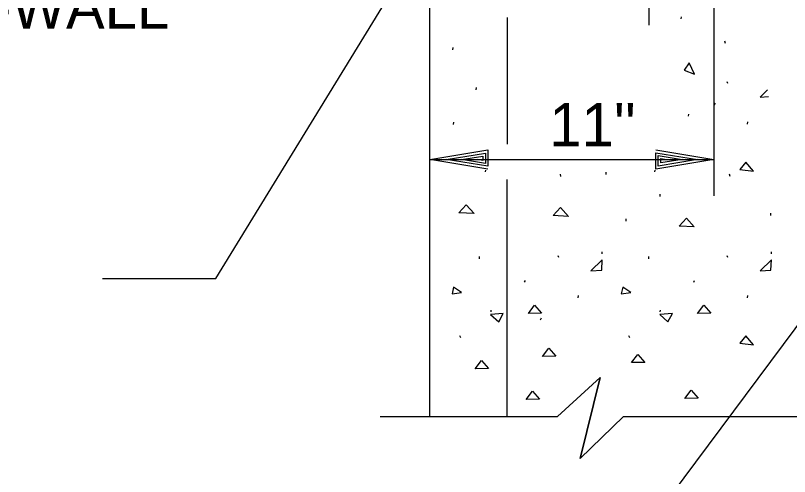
# Model space of a CAD drawing. Extents: x 22369.6 to 22428.3, y 22369.6 to 22415.
# Drawn here: x 22391.587 to 22394.904, y 22374.706 to 22376.682 of the extents above; entities that cross this region are included whole.
import ezdxf

# ---------------------------------------------------------------- set-up
doc = ezdxf.new("R2010")
doc.units = 0
for name, color, linetype in [('Level 1', 7, 'Continuous'), ('Level 10', 7, 'Continuous'), ('Level 4', 7, 'Continuous'), ('Level 8', 7, 'Continuous')]:
    doc.layers.add(name, color=color, linetype=linetype)

msp = doc.modelspace()

# ---------------------------------------------------------------- linework, layer by layer
at = {"layer": 'Level 1'}
for p, q in [((22394.3031, 22376.6397), (22394.3031, 22379.7381)), ((22394.5795, 22378.9163), (22394.5795, 22375.9096)), ((22392.4456, 22375.5546), (22394.1777, 22378.3806)), ((22394.7241, 22376.2165), (22394.7255, 22376.2261)), ((22393.3634, 22376.0646), (22394.5795, 22376.0646)), ((22393.3634, 22376.0646), (22393.3634, 22376.0646)), ((22393.4324, 22376.0646), (22393.4324, 22376.0646)), ((22394.5105, 22376.0646), (22394.5105, 22376.0646)), ((22394.5795, 22376.0646), (22394.5795, 22376.0646)), ((22393.602, 22376.0119), (22393.6033, 22376.0193)), ((22394.3272, 22376.0119), (22394.3285, 22376.0193)), ((22394.1914, 22374.3506), (22395.2279, 22375.7422)), ((22393.9153, 22375.6452), (22393.9125, 22375.6523)), ((22391.9597, 22375.5546), (22392.4456, 22375.5546)), ((22393.9096, 22374.963), (22394.0929, 22375.1307)), ((22394.0073, 22374.7831), (22394.0929, 22375.1307)), ((22394.0929, 22375.1307), (22394.0073, 22374.7831)), ((22393.1508, 22374.963), (22393.9096, 22374.963)), ((22394.1931, 22374.963), (22394.0073, 22374.7831)), ((22394.0073, 22374.7831), (22394.1931, 22374.963)), ((22394.1931, 22374.963), (22395.6847, 22374.963))]:
    msp.add_line(p, q, dxfattribs=at)
for points in [[(22393.6115, 22376.0235), (22393.3634, 22376.0646), (22393.6115, 22376.1057), (22393.6115, 22376.0354), (22393.4324, 22376.0646), (22393.6009, 22376.0924), (22393.6009, 22376.0473), (22393.4987, 22376.0646), (22393.5902, 22376.0792), (22393.5902, 22376.0606), (22393.5677, 22376.0646)], [(22394.3314, 22376.1057), (22394.5795, 22376.0646), (22394.3314, 22376.0235), (22394.3314, 22376.0938), (22394.5105, 22376.0646), (22394.342, 22376.0367), (22394.342, 22376.0818), (22394.4442, 22376.0646), (22394.3526, 22376.05), (22394.3526, 22376.0686), (22394.3752, 22376.0646)]]:
    msp.add_lwpolyline(points, dxfattribs=at)
at = {"layer": 'Level 10'}
for p, q in [((22393.3634, 22374.963), (22393.3634, 22379.6997)), ((22393.695, 22376.6724), (22393.695, 22376.1298)), ((22393.695, 22374.963), (22393.695, 22375.979))]:
    msp.add_line(p, q, dxfattribs=at)
at = {"layer": 'Level 8'}
for p, q in [((22394.4403, 22376.667), (22394.4418, 22376.6766)), ((22394.6305, 22376.5612), (22394.6277, 22376.5712)), ((22393.4609, 22376.5343), (22393.4624, 22376.5439)), ((22394.6405, 22376.3896), (22394.6377, 22376.3967)), ((22393.5616, 22376.3636), (22393.5631, 22376.3733)), ((22394.582, 22376.2981), (22394.587, 22376.3064)), ((22394.4708, 22376.2499), (22394.4723, 22376.2595)), ((22393.464, 22376.2151), (22393.4655, 22376.2247)), ((22393.925, 22375.9921), (22393.9222, 22376.0021)), ((22394.118, 22376.0001), (22394.118, 22376.01)), ((22394.6502, 22375.9921), (22394.6474, 22376.0021)), ((22394.3503, 22375.9063), (22394.3503, 22375.9163)), ((22394.8236, 22375.8248), (22394.8236, 22375.8347)), ((22394.2047, 22375.8003), (22394.2047, 22375.8103)), ((22394.1018, 22375.6598), (22394.1018, 22375.669)), ((22394.827, 22375.6598), (22394.827, 22375.669)), ((22393.5761, 22375.6384), (22393.5761, 22375.6483)), ((22394.3013, 22375.6384), (22394.3013, 22375.6483)), ((22394.6405, 22375.6452), (22394.6377, 22375.6523)), ((22393.7687, 22375.5389), (22393.7723, 22375.5467)), ((22394.4939, 22375.5389), (22394.4975, 22375.5467)), ((22393.9989, 22375.472), (22394.0003, 22375.4816)), ((22394.7241, 22375.472), (22394.7255, 22375.4816)), ((22393.6254, 22375.4115), (22393.6261, 22375.4188)), ((22394.3506, 22375.4115), (22394.3512, 22375.4188)), ((22393.8372, 22375.3783), (22393.8421, 22375.3866)), ((22393.4955, 22375.3007), (22393.4911, 22375.3095)), ((22394.2207, 22375.3007), (22394.2163, 22375.3095))]:
    msp.add_line(p, q, dxfattribs=at)
for points in [[(22394.4525, 22376.4479), (22394.4977, 22376.4303), (22394.4739, 22376.4793)], [(22394.7504, 22376.0153), (22394.7176, 22376.0531), (22394.6912, 22376.0218)], [(22393.4871, 22375.8364), (22393.5186, 22375.8706), (22393.5524, 22375.8328)], [(22393.8916, 22375.8242), (22393.9232, 22375.8584), (22393.957, 22375.8206)], [(22394.4309, 22375.7793), (22394.4625, 22375.8135), (22394.4963, 22375.7757)], [(22394.0994, 22375.5906), (22394.1018, 22375.6349), (22394.0527, 22375.587)], [(22394.8245, 22375.5906), (22394.827, 22375.6349), (22394.7779, 22375.587)], [(22393.4582, 22375.4894), (22393.4985, 22375.4946), (22393.4647, 22375.5173)], [(22394.1834, 22375.4894), (22394.2237, 22375.4946), (22394.1899, 22375.5173)], [(22393.7851, 22375.4045), (22393.8118, 22375.4399), (22393.8418, 22375.4059)], [(22394.5103, 22375.4045), (22394.537, 22375.4399), (22394.567, 22375.4059)], [(22393.6229, 22375.4007), (22393.6582, 22375.3692), (22393.6771, 22375.4045)], [(22394.3481, 22375.4007), (22394.3834, 22375.3692), (22394.4023, 22375.4045)], [(22394.7504, 22375.2709), (22394.7176, 22375.3087), (22394.6912, 22375.2773)], [(22393.8464, 22375.2205), (22393.8731, 22375.2558), (22393.9032, 22375.2218)], [(22394.2277, 22375.1942), (22394.2544, 22375.2295), (22394.2844, 22375.1955)], [(22393.5572, 22375.1679), (22393.5839, 22375.2032), (22393.6139, 22375.1692)], [(22393.7763, 22375.0364), (22393.803, 22375.0717), (22393.833, 22375.0377)], [(22394.4556, 22375.0408), (22394.4823, 22375.0761), (22394.5123, 22375.0421)]]:
    msp.add_lwpolyline(points, close=True, dxfattribs=at)
for points in [[(22394.8102, 22376.3629), (22394.7779, 22376.3314)], [(22394.7779, 22376.3314), (22394.814, 22376.3342)]]:
    msp.add_lwpolyline(points, dxfattribs=at)

# ---------------------------------------------------------------- texts
at = {"layer": 'Level 4'}
for s, p in [('I-WALL', (22391.4179, 22376.6248)), ("11''", (22393.875, 22376.1204))]:
    msp.add_text(s, height=0.18573, dxfattribs=at).set_placement(p)

doc.saveas('drawing.dxf')
